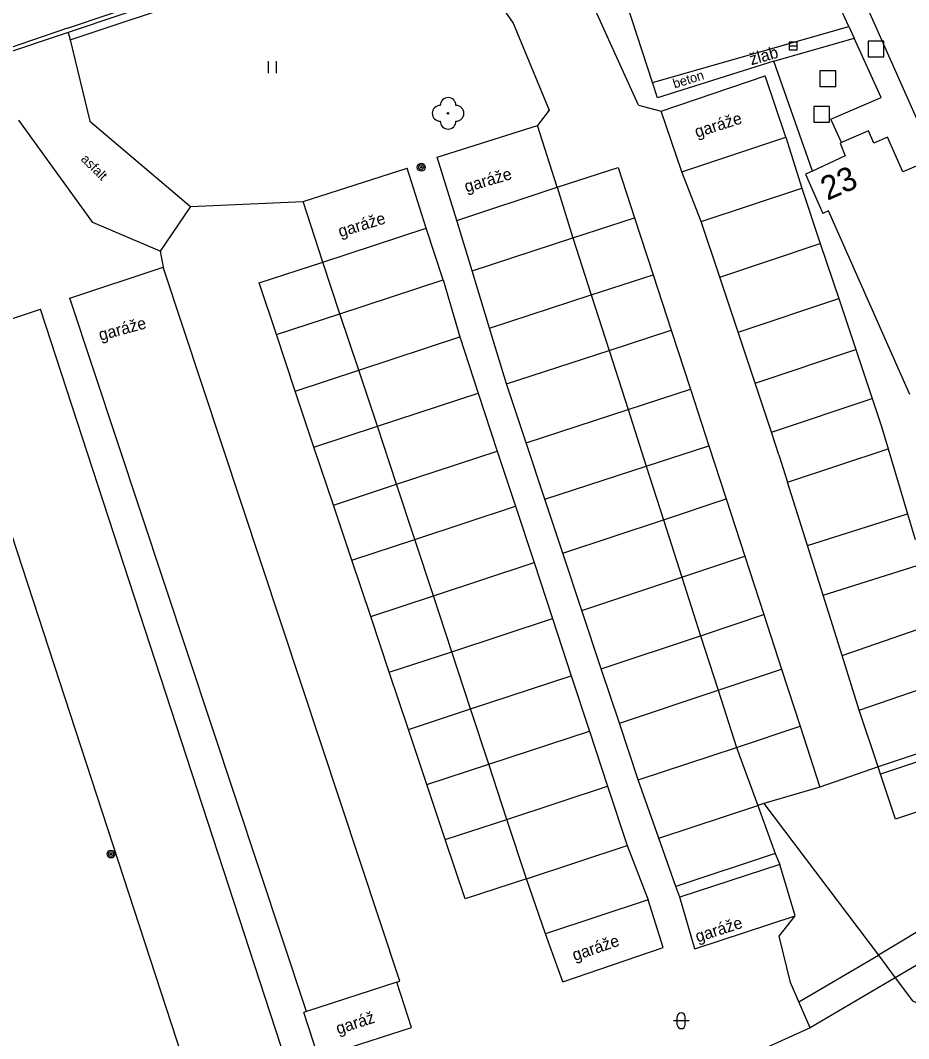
# Model space of a CAD drawing. Extents: x -493753 to -49290, y -1127285 to -112654.
# Drawn here: x -493245.2 to -493189, y -1126749.8 to -1126685.4 of the extents above; entities that cross this region are included whole.
import ezdxf

# ---------------------------------------------------------------- set-up
doc = ezdxf.new("R2010")
doc.units = 0
for name, color, linetype in [('Vrstva 10', 7, 'Continuous'), ('Vrstva 11', 7, 'Continuous'), ('Vrstva 14', 7, 'Continuous'), ('Vrstva 22', 7, 'Continuous'), ('Vrstva 25', 7, 'Continuous'), ('Vrstva 26', 7, 'Continuous'), ('Vrstva 27', 7, 'Continuous'), ('Vrstva 36', 7, 'Continuous'), ('Vrstva 40', 7, 'Continuous'), ('Vrstva 41', 7, 'Continuous'), ('Vrstva 42', 7, 'Continuous'), ('Vrstva 44', 7, 'Continuous'), ('Vrstva 5', 7, 'Continuous'), ('Vrstva 7', 7, 'Continuous')]:
    doc.layers.add(name, color=color, linetype=linetype)

msp = doc.modelspace()

# ---------------------------------------------------------------- linework, layer by layer
at = {"layer": 'Vrstva 10'}
for p, q in [((-493220.15, -1126678.76), (-493242.16, -1126686.18)), ((-493242.16, -1126686.18), (-493249.06, -1126688.48)), ((-493205.16, -1126689.34), (-493192.75, -1126685.8)), ((-493197.48, -1126687.98), (-493192.41, -1126686.54)), ((-493193.88, -1126691.65), (-493190.69, -1126690.29)), ((-493211.72, -1126691.1), (-493212.44, -1126692.06)), ((-493206.06, -1126690.77), (-493204.62, -1126691.15)), ((-493193.2, -1126693.13), (-493193.88, -1126691.65))]:
    msp.add_line(p, q, dxfattribs=at)
for points in [[(-493195.95, -1126674.75), (-493195.88, -1126674.9), (-493187.78, -1126693.13)], [(-493192.75, -1126685.8), (-493197.52, -1126675.4)], [(-493206.06, -1126690.77), (-493209.83, -1126682.45), (-493211.25, -1126678.49)], [(-493216.97, -1126681.3), (-493213.98, -1126685.58), (-493211.72, -1126691.1)], [(-493242.16, -1126686.18), (-493242.03, -1126686.65), (-493240.78, -1126691.79)], [(-493190.69, -1126690.29), (-493192.41, -1126686.54)], [(-493195.05, -1126694.94), (-493197.48, -1126687.98)], [(-493234.42, -1126697.19), (-493236.34, -1126700.02), (-493240.6, -1126698.2), (-493245.28, -1126691.72)], [(-493240.78, -1126691.79), (-493234.42, -1126697.19)]]:
    msp.add_lwpolyline(points, dxfattribs=at)
at = {"layer": 'Vrstva 11'}
for p, q in [((-493242.2, -1126685.91), (-493249.1, -1126688.27)), ((-493192.75, -1126685.8), (-493192.41, -1126686.54)), ((-493196.72, -1126692.8), (-493195.72, -1126696.02)), ((-493195.72, -1126696.02), (-493194.55, -1126699.53)), ((-493234.42, -1126697.19), (-493227.29, -1126696.87)), ((-493194.55, -1126699.53), (-493193.38, -1126703.01)), ((-493236.34, -1126700.02), (-493236.14, -1126701.03))]:
    msp.add_line(p, q, dxfattribs=at)
for points in [[(-493242.2, -1126685.91), (-493220.22, -1126678.5), (-493211.64, -1126675.66), (-493204.82, -1126673.35), (-493197.53, -1126670.9), (-493193.22, -1126669.41), (-493186.91, -1126666.99), (-493176.26, -1126663.62), (-493158.8, -1126657.36)], [(-493203.31, -1126695), (-493196.72, -1126692.8)], [(-493211.21, -1126695.97), (-493207.35, -1126694.71)], [(-493207.35, -1126694.71), (-493206.31, -1126697.9)], [(-493202.08, -1126698.14), (-493203.31, -1126695)], [(-493217.55, -1126698.08), (-493211.21, -1126695.97)], [(-493211.21, -1126695.97), (-493210.21, -1126699.17)], [(-493202.08, -1126698.14), (-493195.72, -1126696.02)], [(-493216.59, -1126701.25), (-493217.55, -1126698.08)], [(-493210.21, -1126699.17), (-493206.31, -1126697.9)], [(-493206.31, -1126697.9), (-493205.13, -1126701.5)], [(-493200.91, -1126701.65), (-493202.08, -1126698.14)], [(-493226.03, -1126700.7), (-493219.49, -1126698.55)], [(-493216.59, -1126701.25), (-493210.21, -1126699.17)], [(-493210.21, -1126699.17), (-493209.05, -1126702.78)], [(-493200.91, -1126701.65), (-493194.55, -1126699.53)], [(-493230.07, -1126702.02), (-493226.03, -1126700.7)], [(-493215.49, -1126704.88), (-493216.59, -1126701.25)], [(-493209.05, -1126702.78), (-493205.13, -1126701.5)], [(-493205.13, -1126701.5), (-493203.99, -1126705.02)], [(-493228.98, -1126705.29), (-493230.07, -1126702.02)], [(-493224.96, -1126703.97), (-493218.43, -1126701.82)], [(-493218.43, -1126701.82), (-493217.37, -1126705.44)], [(-493199.75, -1126705.13), (-493200.91, -1126701.65)], [(-493215.49, -1126704.88), (-493209.05, -1126702.78)], [(-493209.05, -1126702.78), (-493207.92, -1126706.3)], [(-493199.75, -1126705.13), (-493193.38, -1126703.01)], [(-493193.38, -1126703.01), (-493192.3, -1126706.24)], [(-493228.98, -1126705.29), (-493224.96, -1126703.97)], [(-493223.75, -1126707.54), (-493224.96, -1126703.97)], [(-493227.78, -1126708.87), (-493228.98, -1126705.29)], [(-493223.75, -1126707.54), (-493217.37, -1126705.44)], [(-493217.37, -1126705.44), (-493216.21, -1126708.99)], [(-493214.41, -1126708.41), (-493215.49, -1126704.88)], [(-493207.92, -1126706.3), (-493203.99, -1126705.02)], [(-493203.99, -1126705.02), (-493202.77, -1126708.75)], [(-493198.68, -1126708.36), (-493199.75, -1126705.13)], [(-493214.41, -1126708.41), (-493207.92, -1126706.3)], [(-493207.92, -1126706.3), (-493206.72, -1126710.04)], [(-493198.68, -1126708.36), (-493192.3, -1126706.24)], [(-493192.3, -1126706.24), (-493191.26, -1126709.34)], [(-493227.78, -1126708.87), (-493223.75, -1126707.54)], [(-493222.58, -1126711.09), (-493223.75, -1126707.54)], [(-493213.17, -1126712.14), (-493214.41, -1126708.41)], [(-493197.64, -1126711.46), (-493198.68, -1126708.36)], [(-493226.6, -1126712.41), (-493227.78, -1126708.87)], [(-493222.58, -1126711.09), (-493216.21, -1126708.99)], [(-493216.21, -1126708.99), (-493215, -1126712.66)], [(-493206.72, -1126710.04), (-493202.77, -1126708.75)], [(-493202.77, -1126708.75), (-493201.61, -1126712.33)], [(-493197.64, -1126711.46), (-493191.26, -1126709.34)], [(-493191.26, -1126709.34), (-493190.67, -1126711.1), (-493190.25, -1126712.51)], [(-493213.17, -1126712.14), (-493206.72, -1126710.04)], [(-493206.72, -1126710.04), (-493205.57, -1126713.62)], [(-493226.6, -1126712.41), (-493222.58, -1126711.09)], [(-493221.37, -1126714.76), (-493222.58, -1126711.09)], [(-493197.17, -1126712.89), (-493197.64, -1126711.46)], [(-493225.37, -1126716.08), (-493226.6, -1126712.41)], [(-493211.98, -1126715.71), (-493213.17, -1126712.14)], [(-493205.57, -1126713.62), (-493201.61, -1126712.33)], [(-493201.61, -1126712.33), (-493200.51, -1126715.69)], [(-493196.62, -1126714.63), (-493190.25, -1126712.51)], [(-493190.25, -1126712.51), (-493189.03, -1126716.63)], [(-493221.37, -1126714.76), (-493215, -1126712.66)], [(-493215, -1126712.66), (-493213.85, -1126716.15)], [(-493197.17, -1126712.89), (-493196.62, -1126714.63)], [(-493211.98, -1126715.71), (-493205.57, -1126713.62)], [(-493205.57, -1126713.62), (-493204.48, -1126717.02)], [(-493225.37, -1126716.08), (-493221.37, -1126714.76)], [(-493220.22, -1126718.25), (-493221.37, -1126714.76)], [(-493195.36, -1126718.63), (-493196.62, -1126714.63)], [(-493210.84, -1126719.13), (-493211.98, -1126715.71)], [(-493204.48, -1126717.02), (-493200.51, -1126715.69)], [(-493200.51, -1126715.69), (-493199.33, -1126719.32)], [(-493224.21, -1126719.56), (-493225.37, -1126716.08)], [(-493220.22, -1126718.25), (-493213.85, -1126716.15)], [(-493213.85, -1126716.15), (-493212.67, -1126719.72)], [(-493210.84, -1126719.13), (-493204.48, -1126717.02)], [(-493204.48, -1126717.02), (-493203.32, -1126720.65)], [(-493195.36, -1126718.63), (-493189.03, -1126716.63)], [(-493189.03, -1126716.63), (-493188.55, -1126718.25)], [(-493224.21, -1126719.56), (-493220.22, -1126718.25)], [(-493219.04, -1126721.82), (-493220.22, -1126718.25)], [(-493194.37, -1126721.78), (-493195.36, -1126718.63)], [(-493223.01, -1126723.13), (-493224.21, -1126719.56)], [(-493209.64, -1126722.75), (-493210.84, -1126719.13)], [(-493203.32, -1126720.65), (-493199.33, -1126719.32)], [(-493199.33, -1126719.32), (-493198.12, -1126723.01)], [(-493219.04, -1126721.82), (-493212.67, -1126719.72)], [(-493212.67, -1126719.72), (-493211.5, -1126723.26)], [(-493194.37, -1126721.78), (-493188.01, -1126719.78)], [(-493209.64, -1126722.75), (-493203.32, -1126720.65)], [(-493203.32, -1126720.65), (-493202.13, -1126724.35)], [(-493223.01, -1126723.13), (-493219.04, -1126721.82)], [(-493217.88, -1126725.36), (-493219.04, -1126721.82)], [(-493193.17, -1126725.59), (-493194.37, -1126721.78)], [(-493208.41, -1126726.44), (-493209.64, -1126722.75)], [(-493221.83, -1126726.66), (-493223.01, -1126723.13)], [(-493217.88, -1126725.36), (-493211.5, -1126723.26)], [(-493211.5, -1126723.26), (-493210.31, -1126726.88)], [(-493202.13, -1126724.35), (-493198.12, -1126723.01)], [(-493198.12, -1126723.01), (-493197, -1126726.46)], [(-493193.17, -1126725.59), (-493186.77, -1126723.39)], [(-493208.41, -1126726.44), (-493202.13, -1126724.35)], [(-493202.13, -1126724.35), (-493201.02, -1126727.8)], [(-493221.83, -1126726.66), (-493217.88, -1126725.36)], [(-493216.69, -1126728.98), (-493217.88, -1126725.36)], [(-493192.08, -1126729.06), (-493193.17, -1126725.59)], [(-493220.62, -1126730.27), (-493221.83, -1126726.66)], [(-493207.26, -1126729.88), (-493208.41, -1126726.44)], [(-493201.02, -1126727.8), (-493197, -1126726.46)], [(-493197, -1126726.46), (-493195.83, -1126730.06)], [(-493216.69, -1126728.98), (-493210.31, -1126726.88)], [(-493210.31, -1126726.88), (-493209.16, -1126730.38)], [(-493192.08, -1126729.06), (-493185.59, -1126726.83)], [(-493207.26, -1126729.88), (-493201.02, -1126727.8)], [(-493201.02, -1126727.8), (-493199.86, -1126731.41)], [(-493220.62, -1126730.27), (-493216.69, -1126728.98)], [(-493215.53, -1126732.48), (-493216.69, -1126728.98)], [(-493190.89, -1126732.64), (-493192.08, -1126729.06)], [(-493206.07, -1126733.47), (-493207.26, -1126729.88)], [(-493219.45, -1126733.77), (-493220.62, -1126730.27)], [(-493215.53, -1126732.48), (-493209.16, -1126730.38)], [(-493209.16, -1126730.38), (-493208.01, -1126733.86)], [(-493199.86, -1126731.41), (-493195.83, -1126730.06)], [(-493195.83, -1126730.06), (-493194.57, -1126733.93)], [(-493184.33, -1126730.45), (-493190.89, -1126732.64)], [(-493185.04, -1126731.21), (-493190.73, -1126733.11)], [(-493206.07, -1126733.47), (-493199.86, -1126731.41)], [(-493199.86, -1126731.41), (-493198.5, -1126735.08)], [(-493219.45, -1126733.77), (-493215.53, -1126732.48)], [(-493214.39, -1126735.97), (-493215.53, -1126732.48)], [(-493190.89, -1126732.64), (-493194.57, -1126733.93)], [(-493190.73, -1126733.11), (-493190.89, -1126732.64)], [(-493189.78, -1126735.96), (-493190.73, -1126733.11)], [(-493218.29, -1126737.25), (-493219.45, -1126733.77)], [(-493214.39, -1126735.97), (-493208.01, -1126733.86)], [(-493208.01, -1126733.86), (-493206.77, -1126737.62)], [(-493204.77, -1126737.16), (-493206.07, -1126733.47)], [(-493194.57, -1126733.93), (-493198.12, -1126734.97)], [(-493184.09, -1126734.06), (-493189.78, -1126735.96)], [(-493204.77, -1126737.16), (-493198.5, -1126735.08)], [(-493198.12, -1126734.97), (-493198.5, -1126735.08)], [(-493198.5, -1126735.08), (-493197.4, -1126738.13)], [(-493198.12, -1126734.97), (-493190.87, -1126744.55)], [(-493218.29, -1126737.25), (-493214.39, -1126735.97)], [(-493213.15, -1126739.72), (-493214.39, -1126735.97)], [(-493217.03, -1126741), (-493218.29, -1126737.25)], [(-493213.15, -1126739.72), (-493206.77, -1126737.62)], [(-493206.77, -1126737.62), (-493205.45, -1126741.05)], [(-493203.69, -1126740.22), (-493204.77, -1126737.16)], [(-493178.86, -1126737.35), (-493190.87, -1126744.55)], [(-493197.4, -1126738.13), (-493203.69, -1126740.22)], [(-493197.4, -1126738.13), (-493197.11, -1126738.82)], [(-493197.11, -1126738.82), (-493203.45, -1126740.89)], [(-493213.15, -1126739.72), (-493217.03, -1126741)], [(-493211.95, -1126743.21), (-493213.15, -1126739.72)], [(-493203.45, -1126740.89), (-493203.69, -1126740.22)], [(-493205.45, -1126741.05), (-493211.95, -1126743.21)], [(-493195.91, -1126747.52), (-493190.87, -1126744.55)], [(-493190.87, -1126744.55), (-493189.81, -1126746), (-493188.71, -1126747.45), (-493184.68, -1126749.31), (-493175.84, -1126752.77)]]:
    msp.add_lwpolyline(points, dxfattribs=at)
at = {"layer": 'Vrstva 14'}
for p, q in [((-493242.03, -1126686.65), (-493219.97, -1126679.25)), ((-493195.19, -1126749.16), (-493214.37, -1126757.79))]:
    msp.add_line(p, q, dxfattribs=at)
at = {"layer": 'Vrstva 22'}
msp.add_circle((-493218.11, -1126691.29), 0.05, dxfattribs=at)
for centre, start, end in [((-493218.11, -1126690.79), 360, 180), ((-493218.61, -1126691.29), 90, 270), ((-493217.61, -1126691.29), 270, 90), ((-493218.11, -1126691.79), 180, 0)]:
    msp.add_arc(centre, 0.5, start, end, dxfattribs=at)
at = {"layer": 'Vrstva 25'}
for centre, radius in [((-493219.81, -1126694.7), 0.25), ((-493219.81, -1126694.7), 0.158), ((-493219.81, -1126694.7), 0.05), ((-493239.45, -1126738.16), 0.25), ((-493239.45, -1126738.16), 0.158), ((-493239.45, -1126738.16), 0.05)]:
    msp.add_circle(centre, radius, dxfattribs=at)
at = {"layer": 'Vrstva 26'}
for points in [[(-493191.52, -1126687.72), (-493190.52, -1126687.72), (-493190.52, -1126686.72), (-493191.52, -1126686.72)], [(-493194.57, -1126689.6), (-493193.57, -1126689.6), (-493193.57, -1126688.6), (-493194.57, -1126688.6)], [(-493194.96, -1126691.85), (-493193.96, -1126691.85), (-493193.96, -1126690.85), (-493194.96, -1126690.85)]]:
    msp.add_lwpolyline(points, close=True, dxfattribs=at)
at = {"layer": 'Vrstva 27'}
msp.add_line((-493196.51, -1126687.03), (-493196.01, -1126687.03), dxfattribs=at)
msp.add_lwpolyline([(-493196.51, -1126687.28), (-493196.01, -1126687.28), (-493196.01, -1126686.78), (-493196.51, -1126686.78)], close=True, dxfattribs=at)
at = {"layer": 'Vrstva 36'}
for p, q in [((-493229.47, -1126688.74), (-493229.47, -1126687.99)), ((-493228.97, -1126688.74), (-493228.97, -1126687.99)), ((-493203.6, -1126748.96), (-493203.6, -1126748.46)), ((-493203.1, -1126748.96), (-493203.1, -1126748.46)), ((-493202.85, -1126748.71), (-493203.85, -1126748.71))]:
    msp.add_line(p, q, dxfattribs=at)
for centre, start, end in [((-493203.35, -1126748.46), 0, 180), ((-493203.35, -1126748.96), 180, 0)]:
    msp.add_arc(centre, 0.25, start, end, dxfattribs=at)
at = {"layer": 'Vrstva 5'}
for p, q in [((-493191.16, -1126693.17), (-493191.5, -1126692.39)), ((-493193.3, -1126693.17), (-493192.97, -1126693.98)), ((-493190.29, -1126692.79), (-493191.16, -1126693.17)), ((-493189.33, -1126695), (-493190.29, -1126692.79)), ((-493184.69, -1126692.99), (-493189.33, -1126695)), ((-493195.49, -1126695.14), (-493194.39, -1126697.63)), ((-493194.02, -1126697.47), (-493194.39, -1126697.63)), ((-493188.88, -1126709.09), (-493194.02, -1126697.47)), ((-493221.16, -1126746.2), (-493236.14, -1126701.03)), ((-493227.08, -1126748.13), (-493242.05, -1126702.99)), ((-493228.1, -1126752.09), (-493243.91, -1126703.69)), ((-493196.13, -1126742.08), (-493197.11, -1126738.82)), ((-493202.48, -1126744.15), (-493203.45, -1126740.89)), ((-493204.49, -1126744.07), (-493205.45, -1126741.05)), ((-493202.48, -1126744.15), (-493196.13, -1126742.08)), ((-493210.85, -1126746.25), (-493211.95, -1126743.21)), ((-493210.85, -1126746.25), (-493204.49, -1126744.07)), ((-493221.35, -1126746.27), (-493221.16, -1126746.2)), ((-493220.42, -1126749.13), (-493221.35, -1126746.27)), ((-493226.31, -1126751.04), (-493227.24, -1126748.18)), ((-493226.31, -1126751.04), (-493220.42, -1126749.13))]:
    msp.add_line(p, q, dxfattribs=at)
for points in [[(-493204.62, -1126691.15), (-493198.04, -1126688.91)], [(-493196.72, -1126692.8), (-493198.04, -1126688.91)], [(-493203.31, -1126695), (-493204.62, -1126691.15)], [(-493218.81, -1126694.06), (-493212.44, -1126692.06)], [(-493211.21, -1126695.97), (-493212.44, -1126692.06)], [(-493191.5, -1126692.39), (-493193.2, -1126693.13), (-493193.3, -1126693.17)], [(-493217.55, -1126698.08), (-493218.81, -1126694.06)], [(-493192.97, -1126693.98), (-493195.05, -1126694.94), (-493195.49, -1126695.14)], [(-493226.03, -1126700.7), (-493227.29, -1126696.87), (-493220.71, -1126694.75)], [(-493219.49, -1126698.55), (-493220.71, -1126694.75)], [(-493218.43, -1126701.82), (-493219.49, -1126698.55)], [(-493224.96, -1126703.97), (-493226.03, -1126700.7)], [(-493242.05, -1126702.99), (-493236.14, -1126701.03)], [(-493233.93, -1126754.08), (-493249.78, -1126705.63), (-493243.91, -1126703.69)], [(-493221.35, -1126746.27), (-493227.08, -1126748.13)], [(-493227.08, -1126748.13), (-493227.24, -1126748.18)]]:
    msp.add_lwpolyline(points, dxfattribs=at)
at = {"layer": 'Vrstva 7'}
for p, q in [((-493197.16, -1126743.36), (-493196.13, -1126742.08)), ((-493196.44, -1126746.29), (-493197.16, -1126743.36))]:
    msp.add_line(p, q, dxfattribs=at)
for points in [[(-493197.48, -1126687.98), (-493204.85, -1126690.3), (-493205.16, -1126689.34), (-493208.41, -1126679.36), (-493202.71, -1126677.53)], [(-493178.91, -1126739.61), (-493189.81, -1126746), (-493195.19, -1126749.16)], [(-493195.19, -1126749.16), (-493195.91, -1126747.52), (-493196.44, -1126746.29)]]:
    msp.add_lwpolyline(points, dxfattribs=at)

# ---------------------------------------------------------------- texts
at = {"layer": 'Vrstva 40'}
for s, rotation, p in [('beton', 17.47346, (-493203.772, -1126689.723)), ('asfalt', 315.303, (-493241.398, -1126694.235))]:
    msp.add_text(s, height=0.6, rotation=rotation, dxfattribs=at).set_placement(p)
at = {"layer": 'Vrstva 41'}
for s, rotation, p in [('garáže', 17.64114, (-493202.362, -1126692.838)), ('garáže', 16.4628, (-493216.953, -1126696.302)), ('garáže', 17.02423, (-493224.938, -1126699.139)), ('garáže', 15.16356, (-493240.114, -1126705.683)), ('garáže', 18.05515, (-493202.318, -1126743.76)), ('garáže', 18.92004, (-493210.099, -1126744.936)), ('garáž', 17.9991, (-493225.068, -1126749.584))]:
    msp.add_text(s, height=0.75, rotation=rotation, dxfattribs=at).set_placement(p)
at = {"layer": 'Vrstva 42'}
msp.add_text('žlab', height=0.75, rotation=15.88717, dxfattribs=at).set_placement((-493198.914, -1126688.252))
at = {"layer": 'Vrstva 44'}
msp.add_text('23', height=1.5, rotation=23.83801, dxfattribs=at).set_placement((-493194.102, -1126696.832))

doc.saveas('drawing.dxf')
